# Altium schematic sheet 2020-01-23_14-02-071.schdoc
size 322 x 111 mm; SheetNumber: 1; SheetTotal: 1
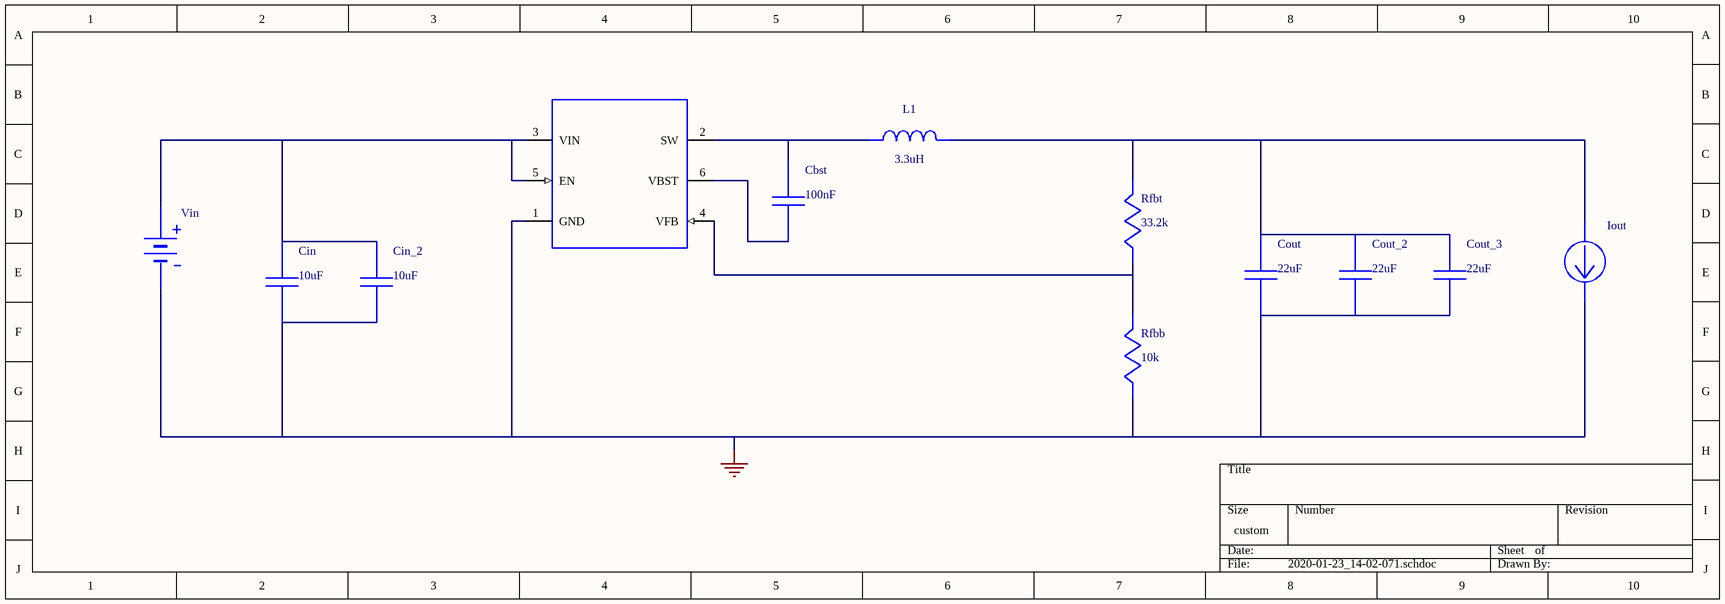
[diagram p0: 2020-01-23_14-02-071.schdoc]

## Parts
Cbst  value 100nF  (hidden comment: C0603C104Z3VACTU)
Cin  value 10uF  (hidden comment: GRM31CR61E106KA12L)
Cin_2  value 10uF  (hidden comment: GRM31CR61E106KA12L)
Cout  value 22uF  (hidden comment: GRM188R60J226MEA0D)
Cout_2  value 22uF  (hidden comment: GRM188R60J226MEA0D)
Cout_3  value 22uF  (hidden comment: GRM188R60J226MEA0D)
Iout  WB_CURRENT_LOAD  (value not drawn)
L1  value 3.3uH  (hidden comment: XAL4030-332MEB)
Rfbb  value 10k  (hidden comment: RC0201FR-0710KL)
Rfbt  value 33.2k  (hidden comment: CRCW040233K2FKED)
U1  TPS562200DDCR  (value not drawn)
Vin  WB_BATTERY  (value not drawn)

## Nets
0: Cin.2 Cin_2.2 Cout.2 Cout_2.2 Cout_3.2 Iout.2(-) Rfbb.2 U1.1(GND) Vin.2(-)
NetCbst_1: Cbst.1 L1.1 U1.2(SW)
NetCbst_2: Cbst.2 U1.6(VBST)
NetCin_1: Cin.1 Cin_2.1 U1.3(VIN) U1.5(EN) Vin.1(+)
NetCout_1: Cout.1 Cout_2.1 Cout_3.1 Iout.1(+) L1.2 Rfbt.1
NetRfbb_1: Rfbb.1 Rfbt.2 U1.4(VFB)

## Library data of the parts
Cbst = C0603C104Z3VACTU: Manufacturer Name: Kemet
Cin Cin_2 = GRM31CR61E106KA12L: GRM31CR61E106KA1; Manufacturer Name: MuRata
Cout Cout_2 Cout_3 = GRM188R60J226MEA0D: GRM188R60J226MEA; Manufacturer Name: MuRata
L1 = XAL4030-332MEB: Manufacturer Name: Coilcraft
Rfbb = RC0201FR-0710KL: Manufacturer Name: Yageo
Rfbt = CRCW040233K2FKED: Manufacturer Name: Vishay-Dale
U1 = TPS562200DDCR: Manufacturer Name: Texas Instruments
